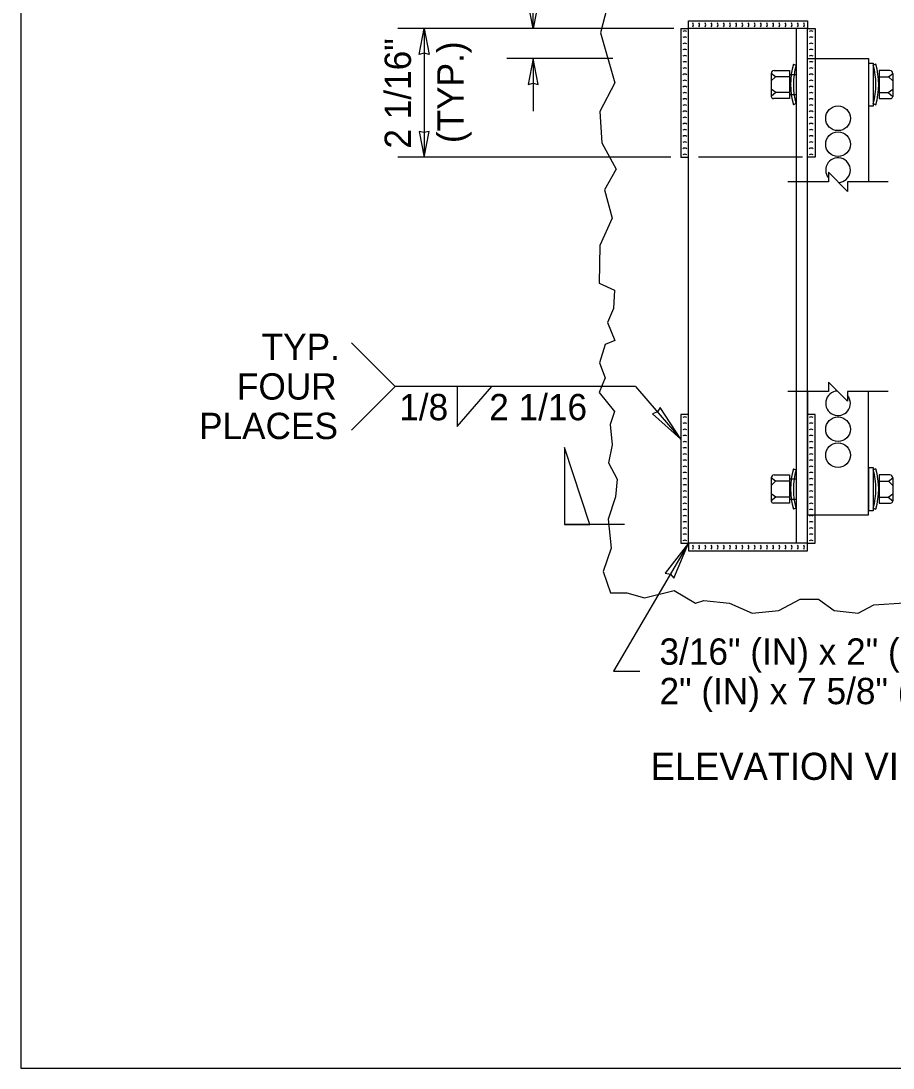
# Model space of a CAD drawing. Extents: x 99862 to 103680, y 99470 to 105076.
# Drawn here: x 99862 to 100392, y 103000 to 103636 of the extents above; entities that cross this region are included whole.
import ezdxf

# ---------------------------------------------------------------- set-up
doc = ezdxf.new("R2010")
doc.units = 0
for name, color, linetype in [('Level 1', 7, 'Continuous'), ('Level 11', 7, 'Continuous'), ('Level 15', 7, 'Continuous'), ('Level 20', 7, 'Continuous'), ('Level 40', 7, 'Continuous'), ('Level 60', 7, 'Continuous')]:
    doc.layers.add(name, color=color, linetype=linetype)

msp = doc.modelspace()

# ---------------------------------------------------------------- linework, layer by layer
at = {"layer": 'Level 1'}
for p, q in [((100267.77, 103631.31), (100267.77, 103635.99)), ((100267.77, 103635.99), (100340.04, 103635.99)), ((100340.04, 103635.99), (100340.04, 103631.31)), ((100263.1, 103631.31), (100263.1, 103553.11)), ((100263.1, 103631.31), (100267.77, 103631.31)), ((100340.04, 103631.31), (100344.71, 103631.31)), ((100344.71, 103631.31), (100344.71, 103613.09)), ((100344.71, 103613.09), (100344.71, 103553.11)), ((100320.65, 103602.06), (100318.02, 103604.1)), ((100318.02, 103604.1), (100318.02, 103590.13)), ((100320.65, 103602.06), (100318.02, 103599.59)), ((100329.1, 103602.06), (100320.65, 103602.06)), ((100329.1, 103605.9), (100329.1, 103588.83)), ((100383.56, 103605.9), (100383.56, 103588.83)), ((100383.56, 103602.06), (100389.27, 103602.06)), ((100389.27, 103602.06), (100391.9, 103604.1)), ((100389.27, 103602.06), (100391.9, 103599.59)), ((100391.9, 103604.1), (100391.9, 103590.13)), ((100320.86, 103592.44), (100318.02, 103594.44)), ((100389.06, 103592.44), (100391.9, 103594.44)), ((100320.86, 103592.44), (100318.02, 103590.13)), ((100329.11, 103588.82), (100319.34, 103588.82)), ((100329.1, 103592.44), (100320.86, 103592.44)), ((100383.56, 103592.44), (100389.06, 103592.44)), ((100383.56, 103588.82), (100390.58, 103588.82)), ((100389.06, 103592.44), (100391.9, 103590.13)), ((100263.1, 103553.11), (100267.77, 103553.11)), ((100344.71, 103553.11), (100340.04, 103553.11)), ((100267.77, 103396.72), (100263.1, 103396.72)), ((100263.1, 103396.72), (100263.1, 103318.52)), ((100344.71, 103396.72), (100340.04, 103396.72)), ((100344.71, 103335.75), (100344.71, 103396.72)), ((100329.1, 103360.01), (100329.1, 103342.94)), ((100383.56, 103360.01), (100383.56, 103342.94)), ((100320.65, 103356.17), (100318.02, 103358.22)), ((100318.02, 103358.22), (100318.02, 103344.24)), ((100320.65, 103356.17), (100318.02, 103353.7)), ((100329.1, 103356.17), (100320.65, 103356.17)), ((100383.56, 103356.17), (100389.27, 103356.17)), ((100389.27, 103356.17), (100391.9, 103358.22)), ((100389.27, 103356.17), (100391.9, 103353.7)), ((100391.9, 103358.22), (100391.9, 103344.24)), ((100320.86, 103346.56), (100318.02, 103348.55)), ((100320.86, 103346.56), (100318.02, 103344.24)), ((100329.1, 103346.56), (100320.86, 103346.56)), ((100383.56, 103346.56), (100389.06, 103346.56)), ((100389.06, 103346.56), (100391.9, 103348.55)), ((100389.06, 103346.56), (100391.9, 103344.24)), ((100329.11, 103342.94), (100319.34, 103342.94)), ((100383.56, 103342.94), (100390.58, 103342.94)), ((100344.71, 103318.52), (100344.71, 103335.75)), ((100263.1, 103318.52), (100267.77, 103318.52)), ((100267.77, 103318.52), (100267.77, 103313.84)), ((100340.04, 103313.84), (100340.04, 103318.52)), ((100340.04, 103318.52), (100344.71, 103318.52)), ((100267.77, 103313.84), (100340.04, 103313.84))]:
    msp.add_line(p, q, dxfattribs=at)
msp.add_lwpolyline([(99862, 102999.5), (103151, 102999.5), (103151, 105075.5), (99862, 105075.5)], close=True, dxfattribs=at)
for centre, radius, start, end in [((100268.43, 103633.65), 2.25, 327.42229, 32.57771), ((100272.18, 103633.65), 2.25, 327.42229, 32.57771), ((100275.93, 103633.65), 2.25, 327.42229, 32.57771), ((100279.68, 103633.65), 2.25, 327.42229, 32.57771), ((100283.43, 103633.65), 2.25, 327.42229, 32.57771), ((100287.18, 103633.65), 2.25, 327.42229, 32.57771), ((100290.93, 103633.65), 2.25, 327.42229, 32.57771), ((100294.68, 103633.65), 2.25, 327.42229, 32.57771), ((100298.43, 103633.65), 2.25, 327.42229, 32.57771), ((100302.18, 103633.65), 2.25, 327.42229, 32.57771), ((100305.93, 103633.65), 2.25, 327.42229, 32.57771), ((100309.68, 103633.65), 2.25, 327.42229, 32.57771), ((100313.43, 103633.65), 2.25, 327.42229, 32.57771), ((100317.18, 103633.65), 2.25, 327.42229, 32.57771), ((100320.93, 103633.65), 2.25, 327.42229, 32.57771), ((100324.68, 103633.65), 2.25, 327.42229, 32.57771), ((100328.43, 103633.65), 2.25, 327.42229, 32.57771), ((100332.18, 103633.65), 2.25, 327.42229, 32.57771), ((100335.93, 103633.65), 2.25, 327.42229, 32.57771), ((100265.44, 103627.68), 2.25, 57.42229, 122.57771), ((100265.44, 103623.93), 2.25, 57.42229, 122.57771), ((100342.37, 103627.68), 2.25, 57.42229, 122.57771), ((100342.37, 103623.93), 2.25, 57.42229, 122.57771), ((100265.44, 103620.18), 2.25, 57.42229, 122.57771), ((100342.37, 103620.18), 2.25, 57.42229, 122.57771), ((100265.44, 103616.43), 2.25, 57.42229, 122.57771), ((100265.44, 103612.68), 2.25, 57.42229, 122.57771), ((100342.37, 103616.43), 2.25, 57.42229, 122.57771), ((100342.37, 103612.68), 2.25, 57.42229, 122.57771), ((100265.44, 103608.93), 2.25, 57.42229, 122.57771), ((100265.44, 103605.18), 2.25, 57.42229, 122.57771), ((100342.37, 103608.93), 2.25, 57.42229, 122.57771), ((100342.37, 103605.18), 2.25, 57.42229, 122.57771), ((100265.44, 103601.43), 2.25, 57.42229, 122.57771), ((100319.77, 103604.15), 1.75, 91.37466, 181.37466), ((100342.37, 103601.43), 2.25, 57.42229, 122.57771), ((100390.15, 103604.15), 1.75, 358.62534, 88.62534), ((100265.44, 103597.68), 2.25, 57.42229, 122.57771), ((100265.44, 103593.93), 2.25, 57.42229, 122.57771), ((100342.37, 103597.68), 2.25, 57.42229, 122.57771), ((100342.37, 103593.93), 2.25, 57.42229, 122.57771), ((100265.44, 103590.18), 2.25, 57.42229, 122.57771), ((100265.44, 103586.43), 2.25, 57.42229, 122.57771), ((100319.34, 103590.13), 1.31, 180, 270), ((100342.37, 103590.18), 2.25, 57.42229, 122.57771), ((100342.37, 103586.43), 2.25, 57.42229, 122.57771), ((100390.58, 103590.13), 1.31, 270, 0), ((100265.44, 103582.68), 2.25, 57.42229, 122.57771), ((100342.37, 103582.68), 2.25, 57.42229, 122.57771), ((100265.44, 103578.93), 2.25, 57.42229, 122.57771), ((100265.44, 103575.18), 2.25, 57.42229, 122.57771), ((100342.37, 103578.93), 2.25, 57.42229, 122.57771), ((100342.37, 103575.18), 2.25, 57.42229, 122.57771), ((100265.44, 103571.43), 2.25, 57.42229, 122.57771), ((100265.44, 103567.68), 2.25, 57.42229, 122.57771), ((100342.37, 103571.43), 2.25, 57.42229, 122.57771), ((100342.37, 103567.68), 2.25, 57.42229, 122.57771), ((100265.44, 103563.93), 2.25, 57.42229, 122.57771), ((100342.37, 103563.93), 2.25, 57.42229, 122.57771), ((100265.44, 103560.18), 2.25, 57.42229, 122.57771), ((100265.44, 103556.43), 2.25, 57.42229, 122.57771), ((100342.37, 103560.18), 2.25, 57.42229, 122.57771), ((100342.37, 103556.43), 2.25, 57.42229, 122.57771), ((100265.44, 103552.68), 2.25, 57.42229, 122.57771), ((100342.37, 103552.68), 2.25, 57.42229, 122.57771), ((100265.44, 103393.08), 2.25, 57.42229, 122.57771), ((100265.44, 103389.33), 2.25, 57.42229, 122.57771), ((100342.37, 103393.08), 2.25, 57.42229, 122.57771), ((100342.37, 103389.33), 2.25, 57.42229, 122.57771), ((100265.44, 103385.58), 2.25, 57.42229, 122.57771), ((100342.37, 103385.58), 2.25, 57.42229, 122.57771), ((100265.44, 103381.83), 2.25, 57.42229, 122.57771), ((100265.44, 103378.08), 2.25, 57.42229, 122.57771), ((100342.37, 103381.83), 2.25, 57.42229, 122.57771), ((100342.37, 103378.08), 2.25, 57.42229, 122.57771), ((100265.44, 103374.33), 2.25, 57.42229, 122.57771), ((100265.44, 103370.58), 2.25, 57.42229, 122.57771), ((100342.37, 103374.33), 2.25, 57.42229, 122.57771), ((100342.37, 103370.58), 2.25, 57.42229, 122.57771), ((100265.44, 103366.83), 2.25, 57.42229, 122.57771), ((100265.44, 103363.08), 2.25, 57.42229, 122.57771), ((100342.37, 103366.83), 2.25, 57.42229, 122.57771), ((100342.37, 103363.08), 2.25, 57.42229, 122.57771), ((100265.44, 103359.33), 2.25, 57.42229, 122.57771), ((100319.77, 103358.26), 1.75, 91.37466, 181.37466), ((100342.37, 103359.33), 2.25, 57.42229, 122.57771), ((100390.15, 103358.26), 1.75, 358.62534, 88.62534), ((100265.44, 103355.58), 2.25, 57.42229, 122.57771), ((100265.44, 103351.83), 2.25, 57.42229, 122.57771), ((100342.37, 103355.58), 2.25, 57.42229, 122.57771), ((100342.37, 103351.83), 2.25, 57.42229, 122.57771), ((100265.44, 103348.08), 2.25, 57.42229, 122.57771), ((100265.44, 103344.33), 2.25, 57.42229, 122.57771), ((100342.37, 103348.08), 2.25, 57.42229, 122.57771), ((100342.37, 103344.33), 2.25, 57.42229, 122.57771), ((100265.44, 103340.58), 2.25, 57.42229, 122.57771), ((100319.34, 103344.24), 1.31, 180, 270), ((100342.37, 103340.58), 2.25, 57.42229, 122.57771), ((100390.58, 103344.24), 1.31, 270, 0), ((100265.44, 103336.83), 2.25, 57.42229, 122.57771), ((100265.44, 103333.08), 2.25, 57.42229, 122.57771), ((100342.37, 103336.83), 2.25, 57.42229, 122.57771), ((100342.37, 103333.08), 2.25, 57.42229, 122.57771), ((100265.44, 103329.33), 2.25, 57.42229, 122.57771), ((100265.44, 103325.58), 2.25, 57.42229, 122.57771), ((100342.37, 103329.33), 2.25, 57.42229, 122.57771), ((100342.37, 103325.58), 2.25, 57.42229, 122.57771), ((100265.44, 103321.83), 2.25, 57.42229, 122.57771), ((100342.37, 103321.83), 2.25, 57.42229, 122.57771), ((100265.44, 103318.08), 2.25, 57.42229, 122.57771), ((100268.43, 103316.18), 2.25, 327.42229, 32.57771), ((100272.18, 103316.18), 2.25, 327.42229, 32.57771), ((100275.93, 103316.18), 2.25, 327.42229, 32.57771), ((100279.68, 103316.18), 2.25, 327.42229, 32.57771), ((100283.43, 103316.18), 2.25, 327.42229, 32.57771), ((100287.18, 103316.18), 2.25, 327.42229, 32.57771), ((100290.93, 103316.18), 2.25, 327.42229, 32.57771), ((100294.68, 103316.18), 2.25, 327.42229, 32.57771), ((100298.43, 103316.18), 2.25, 327.42229, 32.57771), ((100302.18, 103316.18), 2.25, 327.42229, 32.57771), ((100305.93, 103316.18), 2.25, 327.42229, 32.57771), ((100309.68, 103316.18), 2.25, 327.42229, 32.57771), ((100313.43, 103316.18), 2.25, 327.42229, 32.57771), ((100317.18, 103316.18), 2.25, 327.42229, 32.57771), ((100320.93, 103316.18), 2.25, 327.42229, 32.57771), ((100324.68, 103316.18), 2.25, 327.42229, 32.57771), ((100328.43, 103316.18), 2.25, 327.42229, 32.57771), ((100332.18, 103316.18), 2.25, 327.42229, 32.57771), ((100335.93, 103316.18), 2.25, 327.42229, 32.57771), ((100342.37, 103318.08), 2.25, 57.42229, 122.57771)]:
    msp.add_arc(centre, radius, start, end, dxfattribs=at)
at = {"layer": 'Level 11'}
for points in [[(100352.8, 103538.18), (100340.07, 103538.18), (100340.07, 103613.09), (100377.15, 103613.09), (100377.15, 103538.18), (100364.42, 103538.18)], [(100352.8, 103410.66), (100340.07, 103410.66), (100340.07, 103335.75), (100377.15, 103335.75), (100377.15, 103410.66), (100364.42, 103410.66)]]:
    msp.add_lwpolyline(points, dxfattribs=at)
at = {"layer": 'Level 15'}
for p, q in [((100173.37, 103631.31), (100173.37, 103672.5)), ((100258.77, 103631.31), (100091.04, 103631.31)), ((100107.04, 103631.31), (100107.04, 103553.11)), ((100221.66, 103613.09), (100157.37, 103613.09)), ((100173.37, 103613.09), (100173.37, 103581.09)), ((100257.1, 103553.11), (100091.04, 103553.11)), ((100337.04, 103553.11), (100273.77, 103553.11)), ((100267.77, 103318.52), (100222.11, 103240.67)), ((100222.11, 103240.67), (100238.11, 103240.67))]:
    msp.add_line(p, q, dxfattribs=at)
for points in [[(100173.37, 103631.31), (100170.29, 103647.04), (100173.37, 103646.31), (100176.46, 103647.04)], [(100107.04, 103631.31), (100110.12, 103615.59), (100107.04, 103616.32), (100103.95, 103615.59)], [(100173.37, 103613.09), (100170.29, 103597.36), (100173.37, 103598.09), (100176.46, 103597.36)], [(100107.04, 103553.11), (100110.12, 103568.84), (100107.04, 103568.11), (100103.95, 103568.84)], [(100263.1, 103381.79), (100250.47, 103401.05), (100248.9, 103398.3), (100245.95, 103397.16)], [(100267.77, 103318.52), (100253.65, 103300.33), (100256.76, 103299.74), (100258.8, 103297.31)]]:
    msp.add_lwpolyline(points, close=True, dxfattribs=at)
for points in [[(100389.15, 103538.18), (100364.42, 103538.18), (100364.42, 103532.37), (100352.8, 103543.99), (100352.8, 103538.18), (100328.07, 103538.18)], [(100389.15, 103410.66), (100364.42, 103410.66), (100364.42, 103404.85), (100352.8, 103416.47), (100352.8, 103410.66), (100328.07, 103410.66)]]:
    msp.add_lwpolyline(points, dxfattribs=at)
at = {"layer": 'Level 20'}
msp.add_line((100228.84, 103329.82), (100192.31, 103329.82), dxfattribs=at)
msp.add_lwpolyline([(100207.84, 103329.82), (100192.31, 103376.7), (100192.31, 103329.82)], close=True, dxfattribs=at)
at = {"layer": 'Level 40'}
for p, q in [((100214.31, 103628.79), (100222.92, 103598.33)), ((100340.04, 103631.31), (100267.77, 103631.31)), ((100267.77, 103318.52), (100267.77, 103631.31)), ((100333.47, 103318.52), (100333.47, 103631.31)), ((100340.04, 103318.52), (100340.04, 103631.31)), ((100331.51, 103609.68), (100333.07, 103609.07)), ((100381.6, 103609.68), (100380.04, 103609.07)), ((100319.72, 103605.89), (100329.11, 103605.89)), ((100329.17, 103603.52), (100333.47, 103603.52)), ((100390.19, 103605.89), (100383.56, 103605.89)), ((100329.17, 103591.2), (100333.47, 103591.2)), ((100333.07, 103585.74), (100331.51, 103585.05)), ((100380.04, 103585.74), (100381.6, 103585.05)), ((100089.41, 103413.82), (100062.91, 103440.32)), ((100089.41, 103413.82), (100062.91, 103387.31)), ((100235.55, 103413.82), (100089.41, 103413.82)), ((100127.23, 103389.47), (100148.28, 103413.82)), ((100127.23, 103413.82), (100127.23, 103389.47)), ((100235.55, 103413.82), (100263.1, 103381.79)), ((100319.72, 103360.01), (100329.11, 103360.01)), ((100331.51, 103363.8), (100333.07, 103363.18)), ((100381.6, 103363.8), (100380.04, 103363.18)), ((100390.19, 103360.01), (100383.56, 103360.01)), ((100329.17, 103357.64), (100333.47, 103357.64)), ((100329.17, 103345.32), (100333.47, 103345.32)), ((100333.07, 103339.86), (100331.51, 103339.16)), ((100380.04, 103339.86), (100381.6, 103339.16)), ((100340.04, 103318.52), (100267.77, 103318.52))]:
    msp.add_line(p, q, dxfattribs=at)
for points in [[(100221.97, 103672.05), (100222.92, 103669.52), (100220.42, 103660.73), (100226.53, 103647.09), (100218.23, 103644.29), (100214.31, 103628.79)], [(100222.92, 103598.33), (100222.92, 103598.33), (100213.89, 103581.04), (100215.01, 103561.94), (100223.72, 103545.91), (100216.7, 103533.26), (100221.34, 103516.06), (100213.89, 103499.53), (100213.43, 103476.5), (100222.78, 103472.36), (100222.08, 103461.12), (100218.57, 103452.68), (100222.92, 103441.7), (100217.16, 103439.33), (100213.65, 103428.09), (100217.16, 103418.96), (100213.43, 103410.05), (100222.78, 103398.58), (100220.19, 103390.71)], [(100220.19, 103390.71), (100221.35, 103378.24), (100219.2, 103367.32), (100224.33, 103357.54), (100223.37, 103346.64), (100218.81, 103333.18), (100220.69, 103315.57), (100215.95, 103301.3), (100220.3, 103288.45)], [(100220.3, 103288.45), (100230.26, 103288.45), (100240.94, 103285.3), (100259.03, 103289.76), (100271.94, 103282.01), (100277.11, 103283.73), (100292.6, 103282.01), (100306.37, 103275.98), (100322.73, 103277.7), (100335.64, 103284.59), (100346.83, 103284.59), (100356.3, 103277.7), (100370.94, 103275.98), (100380.41, 103281.15), (100398.78, 103282.26), (100409.78, 103285.41), (100414.61, 103295.13)]]:
    msp.add_lwpolyline(points, dxfattribs=at)
for points in [[(100377.36, 103610.39), (100379.91, 103610.39), (100379.91, 103584.17), (100377.36, 103584.17)], [(100377.36, 103364.5), (100379.91, 103364.5), (100379.91, 103338.28), (100377.36, 103338.28)]]:
    msp.add_lwpolyline(points, close=True, dxfattribs=at)
for centre in [(100358.61, 103576.8), (100358.61, 103561.05), (100358.61, 103387.8), (100358.61, 103372.05)]:
    msp.add_circle(centre, 7.5, dxfattribs=at)
for centre, radius, start, end in [((100374.6, 103597.36), 44.82, 164.04769, 195.95252), ((100374.6, 103597.36), 43.14, 164.26237, 195.63726), ((100338.51, 103597.36), 43.14, 344.36274, 15.73763), ((100338.51, 103597.36), 44.82, 344.04748, 15.95231), ((100358.61, 103545.3), 7.5, 272.87528, 219.25899), ((100358.61, 103403.55), 7.5, 92.8753, 39.25897), ((100374.6, 103351.48), 44.82, 164.04769, 195.95252), ((100374.6, 103351.48), 43.14, 164.26237, 195.63726), ((100338.51, 103351.48), 43.14, 344.36274, 15.73763), ((100338.51, 103351.48), 44.82, 344.04748, 15.95231)]:
    msp.add_arc(centre, radius, start, end, dxfattribs=at)
at = {"layer": 'Level 60'}
msp.add_line((99862, 102999.5), (99862, 102999.5), dxfattribs=at)

# ---------------------------------------------------------------- texts
at = {"layer": 'Level 20'}
for s, rotation, p in [('2 1/16"', 90, (100099.04, 103558.38)), ('(TYP.)', 90, (100131.04, 103561.73)), ('TYP.', 360, (100008.3, 103429.82)), ('FOUR', 360, (99993.27, 103405.82)), ('PLACES', 360, (99970.24, 103381.82))]:
    msp.add_text(s, height=16, rotation=rotation, dxfattribs=at).set_placement(p)
for s, height, p in [('1/8', 16, (100091.93, 103393.26)), ('2 1/16', 16, (100146.61, 103393.26)), ('3/16" (IN) x 2" (IN) x ', 16, (100250.11, 103244.67)), ('2" (IN) x 7 5/8" (IN) ANGLE', 16, (100250.11, 103220.67)), ('ELEVATION VIEW', 16.5, (100244.77, 103174.68))]:
    msp.add_text(s, height=height, dxfattribs=at).set_placement(p)

doc.saveas('drawing.dxf')
